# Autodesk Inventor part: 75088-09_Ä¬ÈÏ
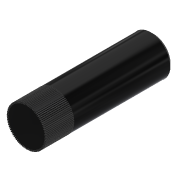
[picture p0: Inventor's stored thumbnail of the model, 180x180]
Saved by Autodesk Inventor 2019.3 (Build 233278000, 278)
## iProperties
Created: 2010-06
Part Number: 75088-09_Ä¬ÈÏ
Material: Ogólny
Document SubType Name: Modeling
Designer: CADENGINEERING4
Density: 1 g/cm^3
Appearance: Gładki — czarny
Author: CADENGINEERING4
Revision Number: ÈÎºÎ
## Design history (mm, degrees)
feature "NONE"
node "Bryła1"
